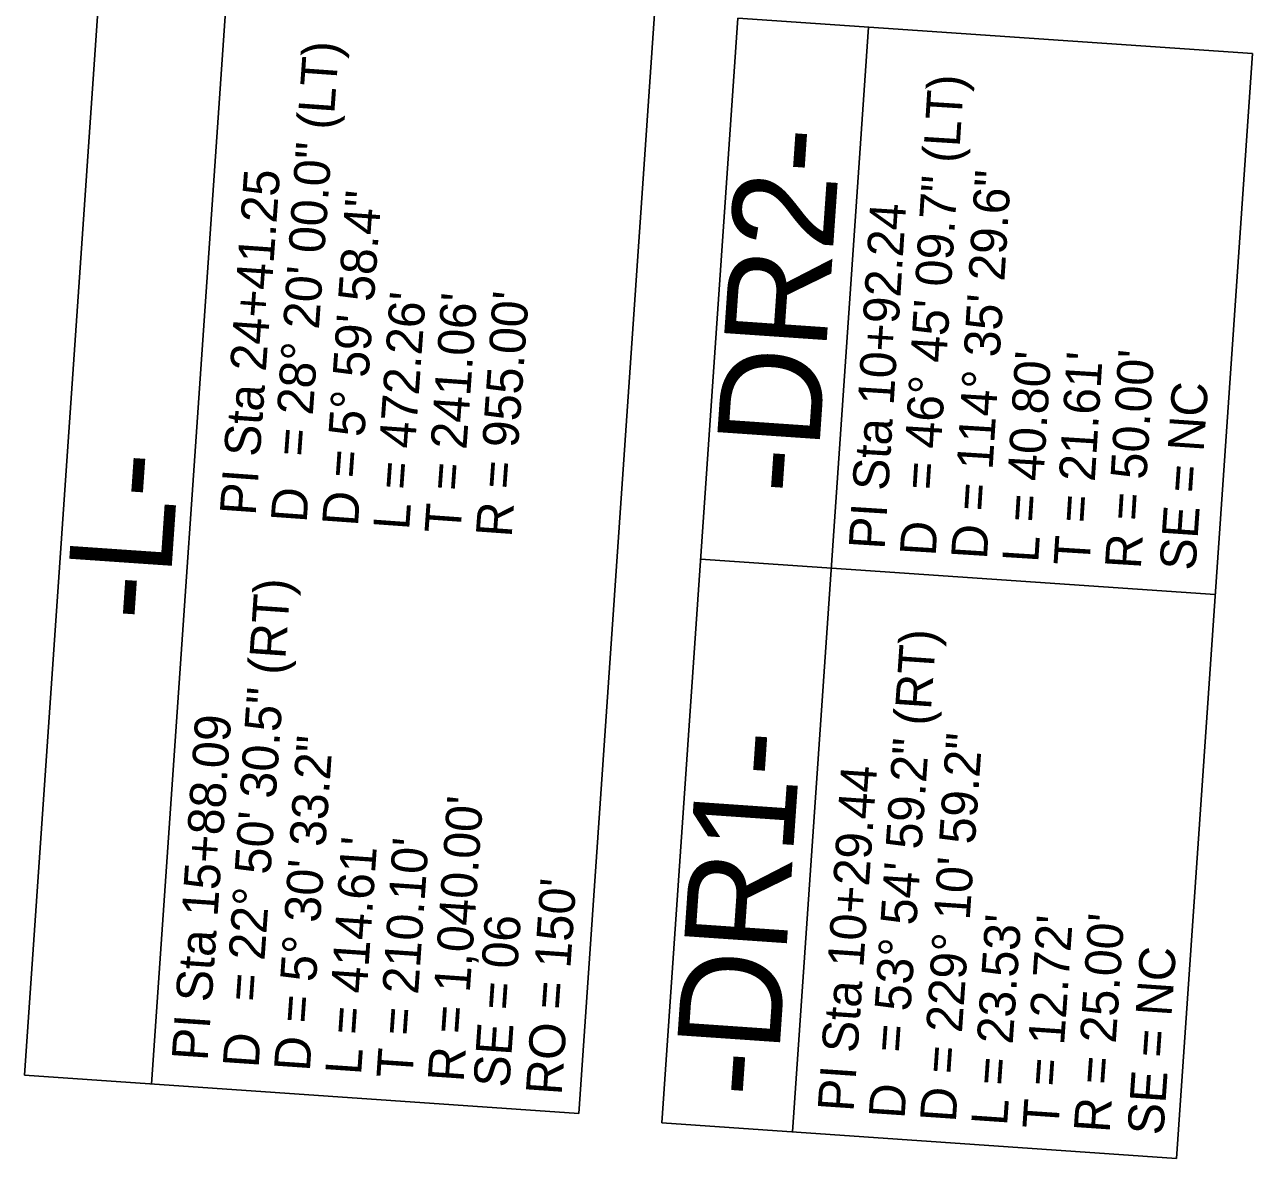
# Model space of a CAD drawing. Extents: x 2599146 to 2600072, y 728518 to 730269.
# Drawn here: x 2599805.6 to 2600044.6, y 729223.4 to 729444 of the extents above; entities that cross this region are included whole.
import ezdxf

# ---------------------------------------------------------------- set-up
doc = ezdxf.new("R2010")
doc.units = 0
doc.layers.add('Old_Level_23', color=7, linetype='Continuous')
doc.layers.add('Prop Horizontal Alignment Curve and Spiral Data', color=7, linetype='Continuous')

msp = doc.modelspace()

# ---------------------------------------------------------------- linework, layer by layer
at = {"layer": 'Old_Level_23'}
for p, q in [((2599805.64, 729239.58), (2599820.44, 729454.39)), ((2599830.37, 729237.87), (2599845.17, 729452.69)), ((2599913.52, 729232.15), (2599928.32, 729446.96)), ((2599929.66, 729230.3), (2599944.47, 729445.24)), ((2599944.47, 729445.24), (2600044.61, 729438.34)), ((2599955.08, 729228.55), (2599969.88, 729443.49)), ((2600029.81, 729223.41), (2600044.61, 729438.34)), ((2599937.22, 729340.01), (2600037.36, 729333.12)), ((2599805.64, 729239.58), (2599913.52, 729232.15)), ((2599929.66, 729230.3), (2600029.81, 729223.41))]:
    msp.add_line(p, q, dxfattribs=at)

# ---------------------------------------------------------------- texts
for s, p in [('-DR2-', (2599959.68, 729352.25)), ('-L-', (2599833.54, 729327.62)), ('-DR1-', (2599951.92, 729234.93))]:
    msp.add_text(s, height=20, rotation=86.0601, dxfattribs=at).set_placement(p)
at = {"layer": 'Prop Horizontal Alignment Curve and Spiral Data'}
for s, rotation, p in [('= 28%%d 20\' 00.0" (LT)', 85.9227, (2599861.15, 729359.8)), ('= 46%%d 45\' 09.7" (LT)', 86.4159, (2599983.46, 729353.3)), ('PI Sta 24+41.25', 85.9227, (2599850.6, 729348.35)), ('D = 114%%d 35\' 29.6"', 86.4159, (2599992.93, 729339.83)), ('D = 5%%d 59\' 58.4"', 85.9227, (2599870.51, 729346.25)), ('PI Sta 10+92.24', 86.4159, (2599973.01, 729341.75)), ("L = 472.26'", 85.9227, (2599880.48, 729345.54)), ("T = 241.06'", 85.9227, (2599890.46, 729344.83)), ("R = 955.00'", 85.9227, (2599900.43, 729344.12)), ("L = 40.80'", 86.4159, (2600002.91, 729339.21)), ("T = 21.61'", 86.4159, (2600012.89, 729338.58)), ("R = 50.00'", 86.4159, (2600022.87, 729337.96)), ('SE = NC', 86.0601, (2600033.5, 729337.65)), ('D', 85.9227, (2599860.53, 729346.97)), ('D', 86.4159, (2599982.95, 729340.46)), ('= 22%%d 50\' 30.5" (RT)', 86.0438, (2599851.77, 729253.74)), ('= 53%%d 54\' 59.2" (RT)', 86.0763, (2599977.48, 729243.86)), ('PI Sta 15+88.09', 86.0438, (2599841.25, 729242.27)), ('D = 5%%d 30\' 33.2"', 86.0438, (2599861.15, 729240.22)), ('D = 229%%d 10\' 59.2"', 86.0763, (2599986.87, 729230.33)), ('PI Sta 10+29.44', 86.0763, (2599966.96, 729232.37)), ("R = 1,040.00'", 86.0438, (2599891.08, 729238.15)), ("L = 414.61'", 86.0438, (2599871.13, 729239.53)), ("T = 210.10'", 86.0438, (2599881.1, 729238.84)), ("RO = 150'", 86.0601, (2599910.16, 729235.61)), ('SE = 06', 86.0601, (2599899.96, 729237.07)), ("L = 23.53'", 86.0763, (2599996.85, 729229.65)), ("T = 12.72'", 86.0763, (2600006.82, 729228.96)), ("R = 25.00'", 86.0763, (2600016.8, 729228.28)), ('SE = NC', 86.0601, (2600027.25, 729227.8)), ('D', 86.0438, (2599851.18, 729240.91)), ('D', 86.0763, (2599976.89, 729231.01))]:
    msp.add_text(s, height=7, rotation=rotation, dxfattribs=at).set_placement(p)

doc.saveas('drawing.dxf')
